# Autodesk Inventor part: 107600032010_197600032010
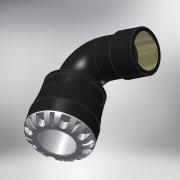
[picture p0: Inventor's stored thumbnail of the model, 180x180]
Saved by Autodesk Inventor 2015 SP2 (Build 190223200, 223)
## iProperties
Created: 2016-12
Part Number: 107600032010_197600032010
Material: PVC-Piping
Description: PLASSON 90° ELBOW WITH FEMALE INTEGRAL BRASS 32X1" SERIES 1
Document SubType Name: Modeling
Designer: KIM
Mass: 664.223 g
Surface Area: 733.008 cm^2
Volume: 474.445 cm^3
Density: 1.4 g/cm^3
Appearance: Black Cast
Author: KIM
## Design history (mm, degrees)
derived "1076.ipt"
feature "Solid1::1076.ipt"
tag "TaggingFeature1"
body "Solid1"
other parameters: "d1" = 22.26, "d2" = 32, "d4" = 58, "d8" = 51.04, "d13" = 7.2, "d14" = 7.2, "d15" = 0, "d17" = 360 deg, "d19" = 8 deg, "d20" = 0.64, "d21" = 0.64, "d22" = 8 deg, "d24" = 0, "d26" = 360 deg, "d33" = 5.8, "d51" = 0.58, "d54" = 11.2, "d55" = 7.04, "d57" = 14.112, "d58" = 0, "d74" = 0, "d78" = 53, "d82" = 0.64, "d115" = 360 deg, "d207" = 90 deg, "d228" = 9.52, "d248" = 3.18, "d270" = 81, "d281" = 4.54365, "d294" = 30.291, "d295" = 19, "d296" = 20.9, "d297" = 27.2619, "d299" = 35.44047, "d300" = 27.2619, "d301" = 0, "d302" = 0, "d306" = 1.96891, "d309" = 53.53, "d310" = 7.79977, "d312" = 15 deg, "d313" = 0.464, "d314" = 5.088, "d315" = 0.29, "d_" = 32, "E_" = 58, "l_" = 53, "A_" = 81, "l_2" = 19, "Rp_" = 30.291, "d9" = 9, "d11" = 58, "d298" = 39.3783
